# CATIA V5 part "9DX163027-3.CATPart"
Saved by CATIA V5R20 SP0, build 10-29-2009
Part number: 9DX163027-3
Revision: ANY
Definition: UNKNOWN
Nomenclature: 9DX163027-3
Source: Unknown
Bounding box of the stored display mesh (mm): x -14.65 to 14.65, y 0 to 32, z -14.65 to 14.65
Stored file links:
  C:\Users\Utente\Desktop\IO LAVORO\3D X SITO CF\CUMSA\3D files DX\DX 163027\9DX163027-3.CATPart
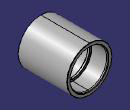
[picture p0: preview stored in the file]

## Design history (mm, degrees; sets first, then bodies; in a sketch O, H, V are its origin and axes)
Body1 "Redondeo2" (main body)
  Solid1: solid without history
